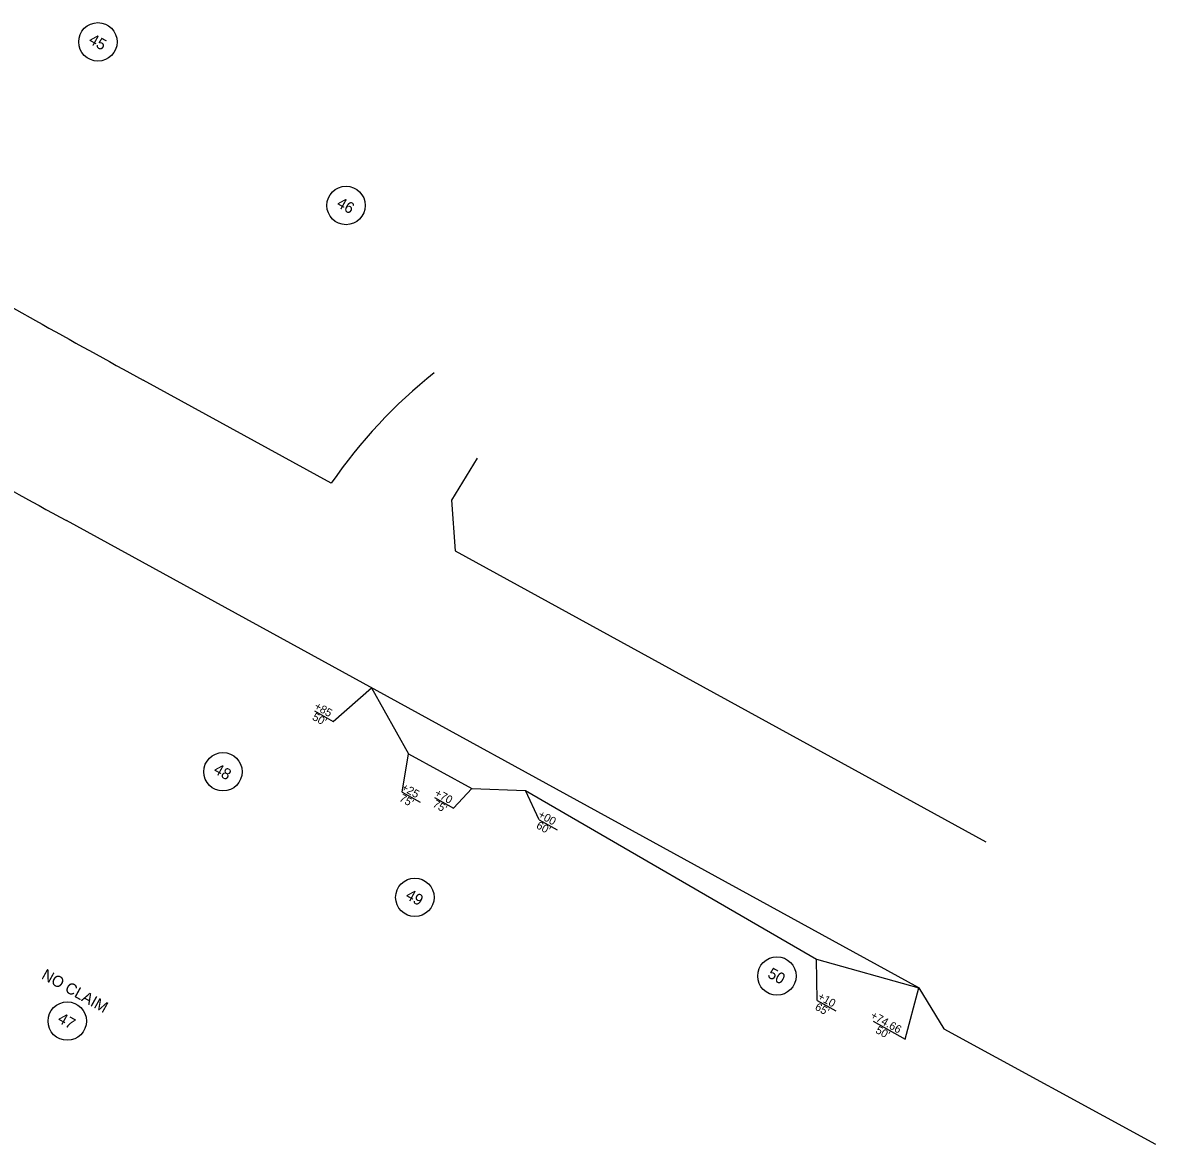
# Model space of a CAD drawing. Extents: x 1762160 to 1765875, y 710174 to 712931.
# Drawn here: x 1765167 to 1765875, y 710174 to 710874 of the extents above; entities that cross this region are included whole.
import ezdxf

# ---------------------------------------------------------------- set-up
doc = ezdxf.new("R2010")
doc.units = 0
for name, color, linetype in [('Exist Other Culture Located Object CELL', 7, 'Continuous'), ('Exist Roads EOP Other', 7, 'Continuous'), ('Exist Utilities Other Pole With Base CELL', 7, 'Continuous'), ('Exist Vegetation Tree CELL', 7, 'Continuous'), ('Exist Vegetation Woods Line', 7, 'Continuous')]:
    doc.layers.add(name, color=color, linetype=linetype)

msp = doc.modelspace()

# ---------------------------------------------------------------- linework, layer by layer
at = {"layer": 'Exist Other Culture Located Object CELL'}
for p, q in [((1765361.12, 710437.61), (1765385.06, 710458.51)), ((1765349.34, 710444.17), (1765361.12, 710437.61)), ((1765404.09, 710393.41), (1765408.13, 710417.36)), ((1765436.21, 710383.41), (1765447.6, 710395.75)), ((1765489.65, 710376.15), (1765481.11, 710394.49)), ((1765404.09, 710393.41), (1765415.35, 710387.14)), ((1765424.34, 710390.02), (1765436.21, 710383.41)), ((1765489.65, 710376.15), (1765500.98, 710369.84)), ((1765663.26, 710263.35), (1765662.89, 710289.21)), ((1765718.3, 710239.26), (1765726.8, 710271.3)), ((1765663.26, 710263.35), (1765674.86, 710256.89)), ((1765698.35, 710250.37), (1765718.3, 710239.26))]:
    msp.add_line(p, q, dxfattribs=at)
at = {"layer": 'Exist Roads EOP Other'}
for p, q in [((1765385.06, 710458.51), (1765408.13, 710417.36)), ((1765408.13, 710417.36), (1765447.6, 710395.75)), ((1765447.6, 710395.75), (1765481.11, 710394.49)), ((1765481.11, 710394.49), (1765662.89, 710289.21)), ((1765662.89, 710289.21), (1765726.8, 710271.3))]:
    msp.add_line(p, q, dxfattribs=at)
at = {"layer": 'Exist Utilities Other Pole With Base CELL'}
for p, q in [((1765067.11, 710748.13), (1765175.16, 710687.85)), ((1765359.86, 710586.33), (1765242.45, 710650.65)), ((1765450.9, 710601.94), (1765434.86, 710575.78)), ((1765434.86, 710575.78), (1765437.15, 710544.07)), ((1765726.8, 710271.3), (1765194.41, 710562.94)), ((1765437.15, 710544.07), (1765768.68, 710362.38)), ((1765726.8, 710271.3), (1765742.46, 710245.62)), ((1765742.46, 710245.62), (1765874.5, 710173.54))]:
    msp.add_line(p, q, dxfattribs=at)
for centre, radius, start, end in [((1770022.75, 719377.11), 9950, 240.843598, 241.286353), ((1765623.37, 710404.78), 320, 128.49446, 145.43482), ((1770022.75, 719377.11), 10050, 240.843598, 241.286353)]:
    msp.add_arc(centre, radius, start, end, dxfattribs=at)
at = {"layer": 'Exist Vegetation Tree CELL'}
for centre in [(1765214.09, 710861.84), (1765369.08, 710759.7), (1765292.19, 710406.15), (1765412.04, 710327.74), (1765638.16, 710278.62), (1765194.94, 710250.49)]:
    msp.add_circle(centre, 12, dxfattribs=at)

# ---------------------------------------------------------------- texts
at = {"layer": 'Exist Other Culture Located Object CELL'}
for s, p in [('+85', (1765348.76, 710445.64)), ("50'", (1765347.51, 710438.9)), ('+25', (1765403.14, 710394.98)), ('+70', (1765423.91, 710391.41)), ("75'", (1765401.88, 710388.24)), ("75'", (1765422.75, 710384.62)), ('+00', (1765488.56, 710378.02)), ("60'", (1765487.39, 710371.23)), ('+10', (1765663.15, 710264.39)), ("65'", (1765661.46, 710257.89)), ('+74.66', (1765696.15, 710252.61)), ("50'", (1765699.29, 710243.43))]:
    msp.add_text(s, height=5, rotation=330.88857, dxfattribs=at).set_placement(p)
at = {"layer": 'Exist Vegetation Woods Line'}
for s, rotation, p in [('45', 330.88857, (1765207.79, 710861.31)), ('46', 330.88857, (1765362.67, 710759.23)), ('48', 330.88857, (1765285.77, 710405.69)), ('49', 330.88857, (1765405.67, 710327.25)), ('NO CLAIM', 330.97208, (1765178.33, 710277.29)), ('50', 330.88857, (1765631.73, 710278.16)), ('47', 330.88857, (1765188.38, 710250.11))]:
    msp.add_text(s, height=7, rotation=rotation, dxfattribs=at).set_placement(p)

doc.saveas('drawing.dxf')
